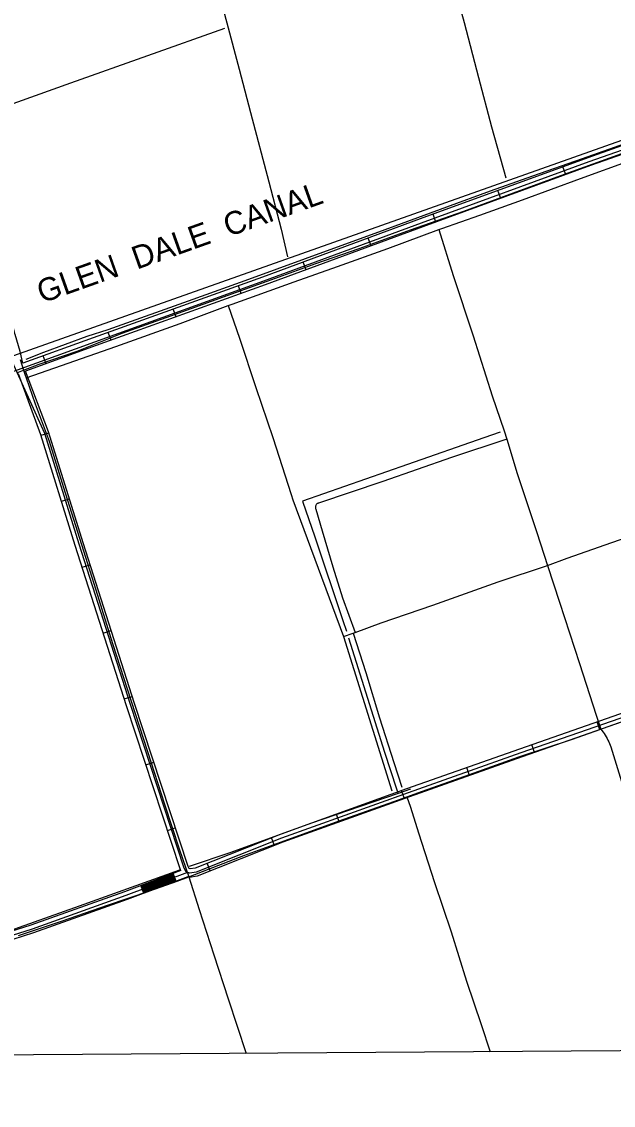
# Model space of a CAD drawing. Extents: x 3508733 to 3546731, y 546897 to 572481.
# Drawn here: x 3539570 to 3541710, y 552296 to 556215 of the extents above; entities that cross this region are included whole.
import ezdxf

# ---------------------------------------------------------------- set-up
doc = ezdxf.new("R2010")
doc.units = 0
for name, color, linetype in [('V-DTCH-CNTR', 7, 'Continuous'), ('V-GRID-FRAM', 7, 'Continuous'), ('V-RIVR-IDEN', 7, 'Continuous'), ('V-ROAD-CNTR', 7, 'Continuous'), ('V-TOPO-BNDY', 7, 'Continuous'), ('V-TOPO-SHOR', 7, 'Continuous')]:
    doc.layers.add(name, color=color, linetype=linetype)

msp = doc.modelspace()

# ---------------------------------------------------------------- linework, layer by layer
at = {"layer": 'V-DTCH-CNTR'}
for points in [[(3540897.2, 557292.4), (3540898.1, 557278.7), (3540899.1, 557265.1), (3540900.4, 557251.5), (3540902, 557237.9), (3540903.7, 557224.4), (3540905.7, 557210.9), (3540907.9, 557197.4), (3540910.4, 557184), (3540913, 557170.6), (3540915.9, 557157.2), (3540919, 557144), (3540922.3, 557130.7), (3540925.9, 557117.5), (3540969.5, 556955.5), (3541013, 556789.8), (3541078.3, 556554.4), (3541115.9, 556409.6), (3541170.5, 556212.2), (3541222.4, 556013.5), (3541269.2, 555835.2), (3541321.1, 555651)], [(3540094.8, 557047.6), (3540132.8, 556914.1), (3540176.8, 556745.2), (3540215.8, 556589.9), (3540268.3, 556372.6), (3540312.3, 556211.5), (3540357.2, 556044), (3540398, 555886.5), (3540463.4, 555635.7), (3540508.4, 555465.5), (3540531.6, 555364.5)], [(3539553.1, 554945.6), (3539577.1, 554954.5), (3539632.7, 554976.6), (3539770.3, 555024.1), (3539933.1, 555088.5), (3540109.1, 555151.2), (3540300, 555219.9), (3540488.2, 555288), (3540633.9, 555340.6), (3540790.9, 555395.4), (3540976.8, 555462.2), (3541169.5, 555530), (3541349.1, 555595.9), (3541533.7, 555664), (3541740.5, 555739.1)], [(3540555.7, 555274.6), (3540712.7, 555329.4), (3540894.6, 555394.9), (3541079, 555463.4), (3541089.1, 555467.2), (3541227.1, 555516), (3541381.4, 555570.9), (3541591.3, 555647.8), (3541770.4, 555713.6)], [(3541079, 555463.4), (3541130.3, 555297.8), (3541202.7, 555079.2), (3541272, 554862), (3541315.3, 554735.8), (3541324.4, 554706), (3541362.5, 554581), (3541433.1, 554367.9), (3541472, 554248.3), (3541515.2, 554115.8), (3541587.7, 553893.7), (3541648.2, 553707.7), (3541664.6, 553656.6)], [(3539585.7, 554927.6), (3539713.8, 554971.4), (3539910.6, 555041), (3540142.7, 555123.5), (3540317.4, 555188.9), (3540330.9, 555193.9), (3540555.7, 555274.6)], [(3540317.4, 555188.9), (3540357.5, 555070.3), (3540417, 554892.5), (3540478.4, 554711.1), (3540545.3, 554504.7), (3540551.3, 554486.2)], [(3539565, 554993.9), (3539577.1, 554954.5), (3539582.5, 554936.9), (3539585.7, 554927.6), (3539618.5, 554832.8), (3539669.6, 554698), (3539721.8, 554531), (3539786.9, 554324.2), (3539837.7, 554160.4), (3539898.2, 553966.7), (3539966.5, 553757.7), (3540025.2, 553575.7), (3540086.1, 553385.7), (3540139.2, 553223.3), (3540174.6, 553121.9), (3540212.1, 553004.7), (3540265.6, 552840.9), (3540317.3, 552681.6), (3540382.2, 552483.8)], [(3541324.4, 554706), (3541124.1, 554638.6), (3540875.8, 554552.7), (3540644.2, 554474.5), (3540642.5, 554473.9), (3540640.8, 554473.2), (3540639.2, 554472.2), (3540637.8, 554471.1), (3540636.4, 554469.8), (3540635.3, 554468.4), (3540634.3, 554466.9), (3540633.5, 554465.2), (3540632.9, 554463.5), (3540632.5, 554461.7), (3540632.3, 554459.9), (3540632.4, 554458), (3540632.6, 554456.2), (3540633.1, 554454.4), (3540633.7, 554452.7), (3540656.7, 554373.8), (3540695.9, 554243.6), (3540731, 554132), (3540775.8, 554006.7)], [(3540551.3, 554486.2), (3540733.7, 553991.7), (3540908.9, 553434.1)], [(3540733.7, 553991.7), (3540769.1, 554004.3), (3540775.8, 554006.7), (3540870.8, 554040.6), (3541057.2, 554105.1), (3541292.9, 554189), (3541472, 554248.3), (3541543.5, 554274.6), (3541704.1, 554331.7), (3541876.1, 554391.2), (3542048, 554451.1)], [(3540769.1, 554004.3), (3540814.8, 553861.3), (3540864.3, 553697.1), (3540916.5, 553535.5), (3540945.1, 553446.8)], [(3539558.2, 552909.7), (3539717.9, 552963.3), (3539880.3, 553019.5), (3540033.3, 553071.6), (3540132.4, 553106.2), (3540174.6, 553121.9), (3540245.2, 553150), (3540373.2, 553199.7), (3540546, 553262.8), (3540718.8, 553325.4), (3540916.6, 553395.5), (3540962.9, 553411.8), (3541020.2, 553431.9), (3541189.4, 553492.7), (3541368.5, 553556.8), (3541561.7, 553620.9), (3541664.6, 553656.6), (3541688, 553664.7), (3541903.8, 553740.8)], [(3541664.6, 553656.6), (3541668.8, 553651.4), (3541672.9, 553646), (3541676.8, 553640.5), (3541680.5, 553634.8), (3541684.1, 553629.1), (3541687.5, 553623.2), (3541690.6, 553617.3), (3541693.6, 553611.2), (3541696.5, 553605.1), (3541699.1, 553598.9), (3541701.5, 553592.5), (3541739.9, 553466.7), (3541796.2, 553286.6), (3541865, 553070.3), (3541914.5, 552901.5), (3541969.4, 552730), (3541992.1, 552656.7)], [(3540962.9, 553411.8), (3540975.8, 553374.2), (3541004.9, 553281), (3541063.1, 553101.4), (3541123, 552923.1), (3541178.9, 552745.7), (3541232, 552587.8), (3541264.9, 552489.8)]]:
    msp.add_lwpolyline(points, dxfattribs=at)
at = {"layer": 'V-GRID-FRAM'}
msp.add_lwpolyline([(3512800, 570478.9), (3544431.3, 570695.1), (3544563.5, 552512.4), (3512916.4, 552296.1), (3512800, 570478.9)], dxfattribs=at)
at = {"layer": 'V-ROAD-CNTR'}
for p, q in [((3541537.8, 555662.1), (3541527.5, 555690.3)), ((3541302.9, 555576.4), (3541292.6, 555604.6)), ((3541068.1, 555490.7), (3541057.8, 555518.9)), ((3540833.5, 555404.5), (3540823.1, 555432.6)), ((3540598.9, 555318), (3540588.5, 555346.1)), ((3540364, 555232.2), (3540353.8, 555260.4)), ((3540128.7, 555147.7), (3540118.5, 555175.9)), ((3539893.4, 555063.2), (3539883.2, 555091.5)), ((3539658.3, 554978.3), (3539648.1, 555006.5)), ((3539640, 554719.5), (3539668.6, 554728.4)), ((3539714.1, 554480.7), (3539742.8, 554489.6)), ((3539788.9, 554242.1), (3539817.5, 554251.2)), ((3539865, 554003.9), (3539893.6, 554013.1)), ((3539941.1, 553765.8), (3539969.6, 553774.9)), ((3541661.5, 553654.4), (3541651.6, 553682.7)), ((3541425.4, 553572.2), (3541415.5, 553600.5)), ((3540019, 553528.1), (3540047.5, 553537.5)), ((3541189.7, 553489), (3541179.7, 553517.3)), ((3540954.1, 553405.5), (3540944, 553433.7)), ((3540718.8, 553321), (3540708.7, 553349.2)), ((3540097, 553290.6), (3540125.5, 553300)), ((3540484.4, 553235.7), (3540473.3, 553263.6)), ((3540251.9, 553143.6), (3540240.9, 553171.5)), ((3540128.6, 553107), (3540118, 553135.1)), ((3540011.6, 553063), (3540001, 553091.1))]:
    msp.add_line(p, q, dxfattribs=at)
for points in [[(3539574.3, 554979.8), (3539564.9, 555022.9), (3539546.2, 555083.9), (3539527.1, 555159.3), (3539512, 555201.6), (3539467.1, 555324.4), (3539379.5, 555597.1), (3539350, 555678.2), (3539345.1, 555704.1), (3539344.1, 555741), (3539346.7, 555777.1), (3539352.9, 555827.4), (3539367, 555913.7), (3539402.7, 556087.5), (3539469.9, 556396.3), (3539520.7, 556652.2), (3539550, 556794.2), (3539569.1, 556859.3), (3539577.7, 556886.1)], [(3536645.7, 553910.5), (3536646.3, 553908.7), (3536978.5, 554025.2), (3537376.5, 554173.7), (3537906.2, 554363.4), (3538526.5, 554585.3), (3539191.2, 554825.2), (3539834.2, 555057.9), (3540445.7, 555277.5), (3541016, 555487.7), (3541622.8, 555709.1), (3541815.1, 555777.3)], [(3541810.1, 555791.4), (3541617.7, 555723.2), (3541010.9, 555501.8), (3540440.6, 555291.6), (3539829.1, 555072), (3539574.3, 554979.8)], [(3541792.7, 555753.4), (3541627.9, 555695), (3541021.2, 555473.7), (3540450.9, 555263.4), (3539839.3, 555043.8), (3539583.4, 554951.2)], [(3542410, 553937.2), (3542245.4, 553875.1), (3541761.5, 553705.1), (3541374.9, 553570.5), (3540967.5, 553426.2), (3540509.9, 553261.9), (3540201, 553139.5), (3540178.4, 553136), (3540165.2, 553140.2), (3540157.9, 553153.4), (3539963.4, 553745.3), (3539778, 554325.7), (3539653.6, 554726.3), (3539535.7, 554986.7)], [(3540145.2, 553145.3), (3540144.1, 553147.4), (3539949.1, 553740.7), (3539763.6, 554321.2), (3539639.5, 554720.9), (3539558.2, 554942)], [(3542390.4, 553945.9), (3542240.3, 553889.2), (3541756.6, 553719.2), (3541370, 553584.7), (3540962.4, 553440.4), (3540504.6, 553276), (3540197, 553154.1), (3540179.6, 553151.3), (3540175.5, 553152.7), (3540171.7, 553159.5), (3539977.6, 553749.9), (3539792.3, 554330.2), (3539667.6, 554731.6), (3539583.4, 554951.2)], [(3542401.5, 553918), (3542250.5, 553861), (3541766.5, 553690.9), (3541379.9, 553556.4), (3540972.5, 553412.1), (3540515.2, 553247.9), (3540204.9, 553125), (3540177.2, 553120.6), (3540170.5, 553122.8)], [(3540145.2, 553145.3), (3539941.7, 553068.8), (3539603.1, 552947.8), (3539415.4, 552888.6), (3538920.3, 552714.4), (3538571.7, 552591.9), (3538239.8, 552477.5)], [(3540170.1, 553138.6), (3539946.8, 553054.7), (3539607.9, 552933.6), (3539420.1, 552874.4), (3538925.3, 552700.3), (3538576.7, 552577.7), (3538271.7, 552472.6)], [(3540170.5, 553122.8), (3539952, 553040.6), (3539612.7, 552919.4), (3539424.9, 552860.2), (3538930.2, 552686.1), (3538581.6, 552563.6), (3538334.2, 552478.3)], [(3540119.1, 553132.3), (3540002.1, 553088.3)], [(3540120.1, 553129.5), (3540003.1, 553085.5)], [(3540121.2, 553126.7), (3540004.2, 553082.7)], [(3540122.2, 553123.9), (3540005.2, 553079.9)], [(3540123.3, 553121.1), (3540006.3, 553077.1)], [(3540124.3, 553118.2), (3540007.3, 553074.2)], [(3540125.4, 553115.4), (3540008.4, 553071.4)], [(3540126.5, 553112.6), (3540009.5, 553068.6)], [(3540127.5, 553109.8), (3540010.5, 553065.8)]]:
    msp.add_lwpolyline(points, dxfattribs=at)
at = {"layer": 'V-TOPO-BNDY'}
msp.add_line((3532484.8, 552511.3), (3544532.5, 556775.4), dxfattribs=at)
at = {"layer": 'V-TOPO-SHOR'}
for points in [[(3540304.1, 556190.7), (3539747, 555993), (3539361.9, 555856)], [(3542007.9, 555869.3), (3541808.5, 555794.3), (3541597.7, 555718.8), (3541417.7, 555656.3), (3541265.1, 555602.4), (3541106.8, 555544.9), (3540860.2, 555454.2), (3540697.9, 555394.9), (3540391, 555282.7), (3540188.5, 555210.3), (3539881.1, 555101.2), (3539805.6, 555076.4), (3539649.5, 555018.5), (3539585.2, 554994)], [(3541300.9, 554731.2), (3541241.3, 554710), (3540965.2, 554613.9), (3540585.4, 554480.8), (3540630.4, 554351.6), (3540732, 554049.4), (3540745, 554011.5)], [(3540752.2, 553986.8), (3540881.9, 553573.4), (3540925.6, 553441), (3540931.7, 553424)], [(3540975.8, 553439), (3540931.7, 553424), (3540614.5, 553315.8), (3540326.9, 553210.7), (3540175.5, 553159.3)], [(3540140.9, 553146), (3539966.5, 553083.5), (3539778.2, 553016.1), (3539561.2, 552939.3), (3539375.9, 552874.2), (3539166.8, 552802.7), (3538919.4, 552717.7), (3538748.2, 552659.7), (3538655.6, 552622.9), (3538487.1, 552566.2), (3538307.6, 552502.9), (3538208.8, 552469)]]:
    msp.add_lwpolyline(points, dxfattribs=at)

# ---------------------------------------------------------------- texts
at = {"layer": 'V-RIVR-IDEN'}
msp.add_text('GLEN  DALE  CANAL', height=83, rotation=19.6142, dxfattribs=at).set_placement((3539643.6, 555196))

doc.saveas('drawing.dxf')
